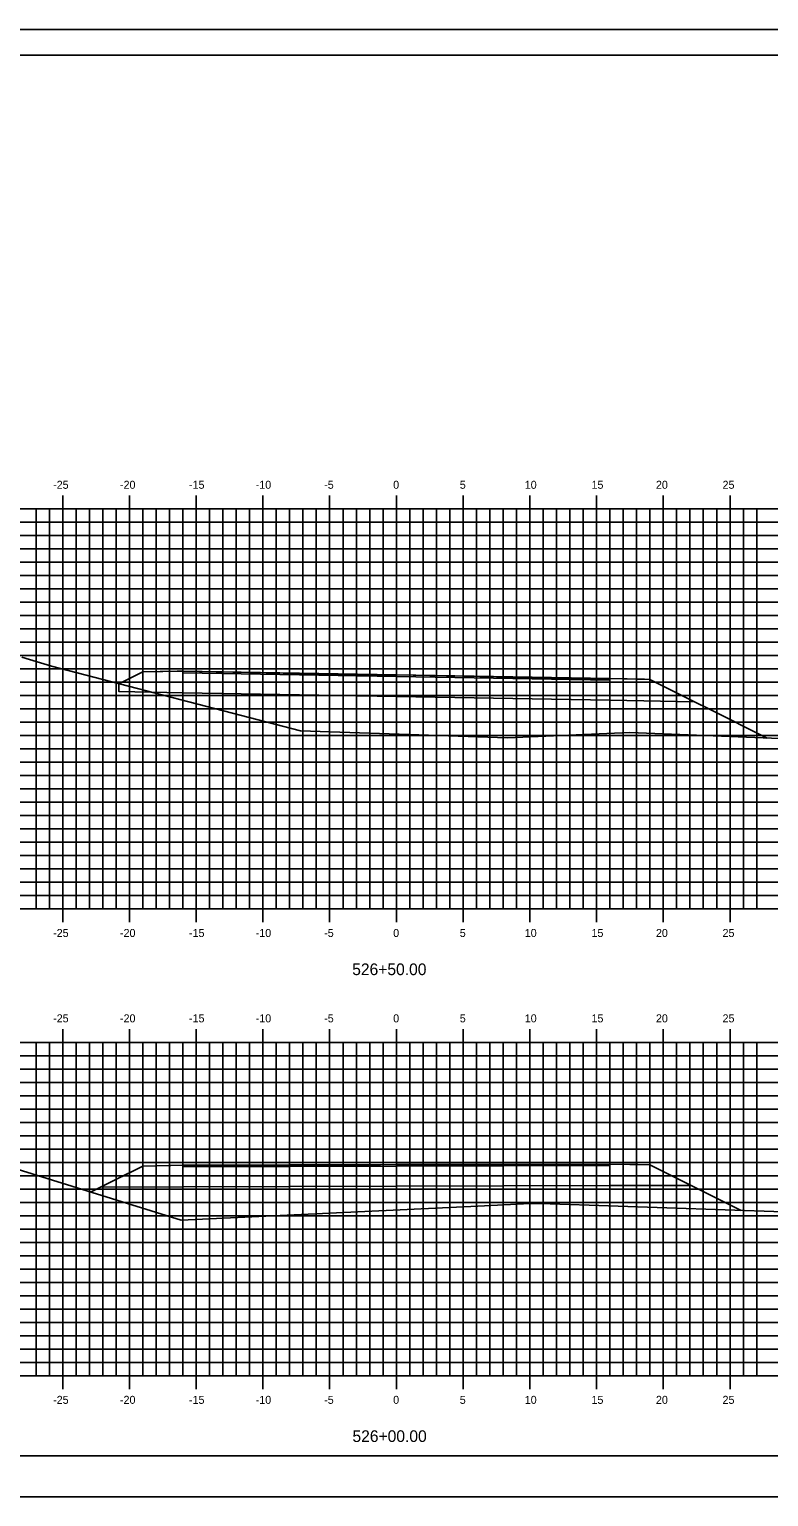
# Model space of a CAD drawing. Extents: x 1168600 to 1177589, y 610178 to 611246.
# Drawn here: x 1175921.1 to 1175976.5, y 610268.7 to 610378.7 of the extents above; entities that cross this region are included whole.
import ezdxf

# ---------------------------------------------------------------- set-up
doc = ezdxf.new("R2010")
doc.units = 0
for name, color, linetype in [('_Construction', 7, 'Continuous'), ('_Station Equation', 7, 'Continuous'), ('D_Roadway_Edge_TW', 7, 'Continuous'), ('D_Roadway_SubGrade', 7, 'Continuous'), ('D_Slope_Direction', 7, 'Continuous'), ('D_Text_Standard', 7, 'Continuous'), ('DIMENSIONS', 7, 'Continuous'), ('H_V ANNOTATION', 7, 'Continuous'), ('MAJOR', 7, 'Continuous'), ('MATCH LINES', 7, 'Continuous'), ('MINOR', 7, 'Continuous')]:
    doc.layers.add(name, color=color, linetype=linetype)

msp = doc.modelspace()

# ---------------------------------------------------------------- linework, layer by layer
at = {"layer": '_Construction'}
for p, q in [((1176033.63, 610376.8), (1175873.63, 610376.8)), ((1175873.63, 610271.8), (1176033.63, 610271.8))]:
    msp.add_line(p, q, dxfattribs=at)
msp.add_lwpolyline([(1175865.54, 610268.74), (1176035.54, 610268.74), (1176035.54, 610378.74), (1175865.54, 610378.74)], close=True, dxfattribs=at)
at = {"layer": '_Station Equation'}
for points in [[(1175920.56, 610331.68), (1175922.78, 610330.99), (1175941.45, 610326.15), (1175956.96, 610325.64), (1175966.12, 610326.02), (1175991.7, 610325.01)], [(1175917.61, 610294.1), (1175932.5, 610289.47), (1175954.73, 610290.51), (1175958.66, 610290.71), (1175960.16, 610290.69), (1175986.39, 610289.8)]]:
    msp.add_lwpolyline(points, dxfattribs=at)
at = {"layer": 'D_Roadway_Edge_TW'}
for points in [[(1175932.63, 610330.51), (1175932.63, 610330.63), (1175948.63, 610330.35), (1175964.63, 610330.07), (1175964.63, 610329.94), (1175948.63, 610330.22)], [(1175932.63, 610293.46), (1175932.63, 610293.59), (1175948.63, 610293.64), (1175964.63, 610293.68), (1175964.63, 610293.56), (1175948.63, 610293.51)]]:
    msp.add_lwpolyline(points, close=True, dxfattribs=at)
at = {"layer": 'D_Roadway_SubGrade'}
for points in [[(1175932.63, 610330.63), (1175929.63, 610330.57), (1175927.84, 610329.68), (1175927.84, 610329.09), (1175932.63, 610329.01)], [(1175932.63, 610329.01), (1175932.63, 610330.51), (1175948.63, 610330.22), (1175964.63, 610329.94), (1175964.63, 610328.44), (1175948.63, 610328.72)], [(1175964.63, 610330.07), (1175967.63, 610330.01), (1175970.98, 610328.33), (1175964.63, 610328.44)], [(1175932.63, 610293.59), (1175929.63, 610293.53), (1175926.46, 610291.94), (1175932.63, 610291.96)], [(1175932.63, 610291.96), (1175932.63, 610293.46), (1175948.63, 610293.51), (1175964.63, 610293.56), (1175964.63, 610292.06), (1175948.63, 610292.01)], [(1175964.63, 610293.68), (1175967.63, 610293.62), (1175970.72, 610292.07), (1175964.63, 610292.06)]]:
    msp.add_lwpolyline(points, close=True, dxfattribs=at)
at = {"layer": 'D_Slope_Direction'}
msp.add_lwpolyline([(1175929.63, 610330.57), (1175927.89, 610329.7)], dxfattribs=at)
at = {"layer": 'D_Text_Standard'}
for points in [[(1175927.84, 610329.68), (1175927.84, 610329.68), (1175927.89, 610329.7), (1175929.14, 610330.33), (1175929.63, 610330.57), (1175932.21, 610330.62), (1175932.63, 610330.63), (1175946.38, 610330.36), (1175948.63, 610330.35), (1175962.38, 610330.07), (1175964.63, 610330.07), (1175967.21, 610330.02), (1175967.63, 610330.01), (1175968.07, 610329.78), (1175970.98, 610328.33), (1175972.09, 610327.77), (1175976.42, 610325.61)], [(1175925.72, 610291.58), (1175926.32, 610291.88), (1175926.46, 610291.94), (1175927.46, 610292.45), (1175929.63, 610293.53), (1175931.73, 610293.57), (1175932.63, 610293.59), (1175943.83, 610293.55), (1175948.63, 610293.64), (1175959.83, 610293.6), (1175964.63, 610293.68), (1175966.73, 610293.64), (1175967.63, 610293.62), (1175968.51, 610293.18), (1175970.72, 610292.07), (1175973.17, 610290.85), (1175974.47, 610290.2)]]:
    msp.add_lwpolyline(points, dxfattribs=at)
at = {"layer": 'DIMENSIONS'}
for points in [[(1175932.63, 610330.51), (1175932.63, 610330.51), (1175948.63, 610330.22), (1175964.63, 610329.94), (1175964.63, 610329.94), (1175948.63, 610330.22)], [(1175932.63, 610293.46), (1175932.63, 610293.46), (1175948.63, 610293.51), (1175964.63, 610293.56), (1175964.63, 610293.56), (1175948.63, 610293.51)]]:
    msp.add_lwpolyline(points, close=True, dxfattribs=at)
for points in [[(1175932.63, 610330.51), (1175932.63, 610330.51)], [(1175932.63, 610330.51), (1175932.63, 610330.51)], [(1175964.63, 610329.94), (1175964.63, 610329.94)], [(1175964.63, 610329.94), (1175964.63, 610329.94)], [(1175932.63, 610293.46), (1175932.63, 610293.46)], [(1175932.63, 610293.46), (1175932.63, 610293.46)], [(1175964.63, 610293.56), (1175964.63, 610293.56)], [(1175964.63, 610293.56), (1175964.63, 610293.56)]]:
    msp.add_lwpolyline(points, dxfattribs=at)
at = {"layer": 'MAJOR'}
for p, q in [((1175923.63, 610343.8), (1175923.63, 610342.8)), ((1175928.63, 610343.8), (1175928.63, 610342.8)), ((1175933.63, 610343.8), (1175933.63, 610342.8)), ((1175938.63, 610343.8), (1175938.63, 610342.8)), ((1175943.63, 610343.8), (1175943.63, 610342.8)), ((1175948.63, 610343.8), (1175948.63, 610342.8)), ((1175953.63, 610343.8), (1175953.63, 610342.8)), ((1175958.63, 610343.8), (1175958.63, 610342.8)), ((1175963.63, 610343.8), (1175963.63, 610342.8)), ((1175968.63, 610343.8), (1175968.63, 610342.8)), ((1175973.63, 610343.8), (1175973.63, 610342.8)), ((1175878.63, 610342.8), (1176018.63, 610342.8)), ((1175878.63, 610342.8), (1176018.63, 610342.8)), ((1175923.63, 610312.8), (1175923.63, 610342.8)), ((1175928.63, 610312.8), (1175928.63, 610342.8)), ((1175933.63, 610312.8), (1175933.63, 610342.8)), ((1175938.63, 610312.8), (1175938.63, 610342.8)), ((1175943.63, 610312.8), (1175943.63, 610342.8)), ((1175948.63, 610312.8), (1175948.63, 610342.8)), ((1175953.63, 610312.8), (1175953.63, 610342.8)), ((1175958.63, 610312.8), (1175958.63, 610342.8)), ((1175963.63, 610312.8), (1175963.63, 610342.8)), ((1175968.63, 610312.8), (1175968.63, 610342.8)), ((1175973.63, 610312.8), (1175973.63, 610342.8)), ((1175878.63, 610337.8), (1176018.63, 610337.8)), ((1175878.63, 610332.8), (1176018.63, 610332.8)), ((1175878.63, 610327.8), (1176018.63, 610327.8)), ((1175878.63, 610322.8), (1176018.63, 610322.8)), ((1175878.63, 610317.8), (1176018.63, 610317.8)), ((1175878.63, 610312.8), (1176018.63, 610312.8)), ((1175878.63, 610312.8), (1176018.63, 610312.8)), ((1175923.63, 610311.8), (1175923.63, 610312.8)), ((1175928.63, 610311.8), (1175928.63, 610312.8)), ((1175933.63, 610311.8), (1175933.63, 610312.8)), ((1175938.63, 610311.8), (1175938.63, 610312.8)), ((1175943.63, 610311.8), (1175943.63, 610312.8)), ((1175948.63, 610311.8), (1175948.63, 610312.8)), ((1175953.63, 610311.8), (1175953.63, 610312.8)), ((1175958.63, 610311.8), (1175958.63, 610312.8)), ((1175963.63, 610311.8), (1175963.63, 610312.8)), ((1175968.63, 610311.8), (1175968.63, 610312.8)), ((1175973.63, 610311.8), (1175973.63, 610312.8)), ((1175923.63, 610303.8), (1175923.63, 610302.8)), ((1175928.63, 610303.8), (1175928.63, 610302.8)), ((1175933.63, 610303.8), (1175933.63, 610302.8)), ((1175938.63, 610303.8), (1175938.63, 610302.8)), ((1175943.63, 610303.8), (1175943.63, 610302.8)), ((1175948.63, 610303.8), (1175948.63, 610302.8)), ((1175953.63, 610303.8), (1175953.63, 610302.8)), ((1175958.63, 610303.8), (1175958.63, 610302.8)), ((1175963.63, 610303.8), (1175963.63, 610302.8)), ((1175968.63, 610303.8), (1175968.63, 610302.8)), ((1175973.63, 610303.8), (1175973.63, 610302.8)), ((1175878.63, 610302.8), (1176018.63, 610302.8)), ((1175878.63, 610302.8), (1176018.63, 610302.8)), ((1175923.63, 610277.8), (1175923.63, 610302.8)), ((1175928.63, 610277.8), (1175928.63, 610302.8)), ((1175933.63, 610277.8), (1175933.63, 610302.8)), ((1175938.63, 610277.8), (1175938.63, 610302.8)), ((1175943.63, 610277.8), (1175943.63, 610302.8)), ((1175948.63, 610277.8), (1175948.63, 610302.8)), ((1175953.63, 610277.8), (1175953.63, 610302.8)), ((1175958.63, 610277.8), (1175958.63, 610302.8)), ((1175963.63, 610277.8), (1175963.63, 610302.8)), ((1175968.63, 610277.8), (1175968.63, 610302.8)), ((1175973.63, 610277.8), (1175973.63, 610302.8)), ((1175878.63, 610297.8), (1176018.63, 610297.8)), ((1175878.63, 610292.8), (1176018.63, 610292.8)), ((1175878.63, 610287.8), (1176018.63, 610287.8)), ((1175878.63, 610282.8), (1176018.63, 610282.8)), ((1175878.63, 610277.8), (1176018.63, 610277.8)), ((1175878.63, 610277.8), (1176018.63, 610277.8)), ((1175923.63, 610276.8), (1175923.63, 610277.8)), ((1175928.63, 610276.8), (1175928.63, 610277.8)), ((1175933.63, 610276.8), (1175933.63, 610277.8)), ((1175938.63, 610276.8), (1175938.63, 610277.8)), ((1175943.63, 610276.8), (1175943.63, 610277.8)), ((1175948.63, 610276.8), (1175948.63, 610277.8)), ((1175953.63, 610276.8), (1175953.63, 610277.8)), ((1175958.63, 610276.8), (1175958.63, 610277.8)), ((1175963.63, 610276.8), (1175963.63, 610277.8)), ((1175968.63, 610276.8), (1175968.63, 610277.8)), ((1175973.63, 610276.8), (1175973.63, 610277.8))]:
    msp.add_line(p, q, dxfattribs=at)
at = {"layer": 'MATCH LINES'}
for points in [[(1175932.63, 610330.63), (1175932.63, 610330.51)], [(1175964.63, 610330.07), (1175964.63, 610329.94)], [(1175932.63, 610293.59), (1175932.63, 610293.46)], [(1175964.63, 610293.68), (1175964.63, 610293.56)]]:
    msp.add_lwpolyline(points, dxfattribs=at)
at = {"layer": 'MINOR'}
for p, q in [((1175921.63, 610312.8), (1175921.63, 610342.8)), ((1175922.63, 610312.8), (1175922.63, 610342.8)), ((1175924.63, 610312.8), (1175924.63, 610342.8)), ((1175925.63, 610312.8), (1175925.63, 610342.8)), ((1175926.63, 610312.8), (1175926.63, 610342.8)), ((1175927.63, 610312.8), (1175927.63, 610342.8)), ((1175929.63, 610312.8), (1175929.63, 610342.8)), ((1175930.63, 610312.8), (1175930.63, 610342.8)), ((1175931.63, 610312.8), (1175931.63, 610342.8)), ((1175932.63, 610312.8), (1175932.63, 610342.8)), ((1175934.63, 610312.8), (1175934.63, 610342.8)), ((1175935.63, 610312.8), (1175935.63, 610342.8)), ((1175936.63, 610312.8), (1175936.63, 610342.8)), ((1175937.63, 610312.8), (1175937.63, 610342.8)), ((1175939.63, 610312.8), (1175939.63, 610342.8)), ((1175940.63, 610312.8), (1175940.63, 610342.8)), ((1175941.63, 610312.8), (1175941.63, 610342.8)), ((1175942.63, 610312.8), (1175942.63, 610342.8)), ((1175944.63, 610312.8), (1175944.63, 610342.8)), ((1175945.63, 610312.8), (1175945.63, 610342.8)), ((1175946.63, 610312.8), (1175946.63, 610342.8)), ((1175947.63, 610312.8), (1175947.63, 610342.8)), ((1175949.63, 610312.8), (1175949.63, 610342.8)), ((1175950.63, 610312.8), (1175950.63, 610342.8)), ((1175951.63, 610312.8), (1175951.63, 610342.8)), ((1175952.63, 610312.8), (1175952.63, 610342.8)), ((1175954.63, 610312.8), (1175954.63, 610342.8)), ((1175955.63, 610312.8), (1175955.63, 610342.8)), ((1175956.63, 610312.8), (1175956.63, 610342.8)), ((1175957.63, 610312.8), (1175957.63, 610342.8)), ((1175959.63, 610312.8), (1175959.63, 610342.8)), ((1175960.63, 610312.8), (1175960.63, 610342.8)), ((1175961.63, 610312.8), (1175961.63, 610342.8)), ((1175962.63, 610312.8), (1175962.63, 610342.8)), ((1175964.63, 610312.8), (1175964.63, 610342.8)), ((1175965.63, 610312.8), (1175965.63, 610342.8)), ((1175966.63, 610312.8), (1175966.63, 610342.8)), ((1175967.63, 610312.8), (1175967.63, 610342.8)), ((1175969.63, 610312.8), (1175969.63, 610342.8)), ((1175970.63, 610312.8), (1175970.63, 610342.8)), ((1175971.63, 610312.8), (1175971.63, 610342.8)), ((1175972.63, 610312.8), (1175972.63, 610342.8)), ((1175974.63, 610312.8), (1175974.63, 610342.8)), ((1175975.63, 610312.8), (1175975.63, 610342.8)), ((1175878.63, 610341.8), (1176018.63, 610341.8)), ((1175878.63, 610340.8), (1176018.63, 610340.8)), ((1175878.63, 610339.8), (1176018.63, 610339.8)), ((1175878.63, 610338.8), (1176018.63, 610338.8)), ((1175878.63, 610336.8), (1176018.63, 610336.8)), ((1175878.63, 610335.8), (1176018.63, 610335.8)), ((1175878.63, 610334.8), (1176018.63, 610334.8)), ((1175878.63, 610333.8), (1176018.63, 610333.8)), ((1175878.63, 610331.8), (1176018.63, 610331.8)), ((1175878.63, 610330.8), (1176018.63, 610330.8)), ((1175878.63, 610329.8), (1176018.63, 610329.8)), ((1175878.63, 610328.8), (1176018.63, 610328.8)), ((1175878.63, 610326.8), (1176018.63, 610326.8)), ((1175878.63, 610325.8), (1176018.63, 610325.8)), ((1175878.63, 610324.8), (1176018.63, 610324.8)), ((1175878.63, 610323.8), (1176018.63, 610323.8)), ((1175878.63, 610321.8), (1176018.63, 610321.8)), ((1175878.63, 610320.8), (1176018.63, 610320.8)), ((1175878.63, 610319.8), (1176018.63, 610319.8)), ((1175878.63, 610318.8), (1176018.63, 610318.8)), ((1175878.63, 610316.8), (1176018.63, 610316.8)), ((1175878.63, 610315.8), (1176018.63, 610315.8)), ((1175878.63, 610314.8), (1176018.63, 610314.8)), ((1175878.63, 610313.8), (1176018.63, 610313.8)), ((1175921.63, 610277.8), (1175921.63, 610302.8)), ((1175922.63, 610277.8), (1175922.63, 610302.8)), ((1175924.63, 610277.8), (1175924.63, 610302.8)), ((1175925.63, 610277.8), (1175925.63, 610302.8)), ((1175926.63, 610277.8), (1175926.63, 610302.8)), ((1175927.63, 610277.8), (1175927.63, 610302.8)), ((1175929.63, 610277.8), (1175929.63, 610302.8)), ((1175930.63, 610277.8), (1175930.63, 610302.8)), ((1175931.63, 610277.8), (1175931.63, 610302.8)), ((1175932.63, 610277.8), (1175932.63, 610302.8)), ((1175934.63, 610277.8), (1175934.63, 610302.8)), ((1175935.63, 610277.8), (1175935.63, 610302.8)), ((1175936.63, 610277.8), (1175936.63, 610302.8)), ((1175937.63, 610277.8), (1175937.63, 610302.8)), ((1175939.63, 610277.8), (1175939.63, 610302.8)), ((1175940.63, 610277.8), (1175940.63, 610302.8)), ((1175941.63, 610277.8), (1175941.63, 610302.8)), ((1175942.63, 610277.8), (1175942.63, 610302.8)), ((1175944.63, 610277.8), (1175944.63, 610302.8)), ((1175945.63, 610277.8), (1175945.63, 610302.8)), ((1175946.63, 610277.8), (1175946.63, 610302.8)), ((1175947.63, 610277.8), (1175947.63, 610302.8)), ((1175949.63, 610277.8), (1175949.63, 610302.8)), ((1175950.63, 610277.8), (1175950.63, 610302.8)), ((1175951.63, 610277.8), (1175951.63, 610302.8)), ((1175952.63, 610277.8), (1175952.63, 610302.8)), ((1175954.63, 610277.8), (1175954.63, 610302.8)), ((1175955.63, 610277.8), (1175955.63, 610302.8)), ((1175956.63, 610277.8), (1175956.63, 610302.8)), ((1175957.63, 610277.8), (1175957.63, 610302.8)), ((1175959.63, 610277.8), (1175959.63, 610302.8)), ((1175960.63, 610277.8), (1175960.63, 610302.8)), ((1175961.63, 610277.8), (1175961.63, 610302.8)), ((1175962.63, 610277.8), (1175962.63, 610302.8)), ((1175964.63, 610277.8), (1175964.63, 610302.8)), ((1175965.63, 610277.8), (1175965.63, 610302.8)), ((1175966.63, 610277.8), (1175966.63, 610302.8)), ((1175967.63, 610277.8), (1175967.63, 610302.8)), ((1175969.63, 610277.8), (1175969.63, 610302.8)), ((1175970.63, 610277.8), (1175970.63, 610302.8)), ((1175971.63, 610277.8), (1175971.63, 610302.8)), ((1175972.63, 610277.8), (1175972.63, 610302.8)), ((1175974.63, 610277.8), (1175974.63, 610302.8)), ((1175975.63, 610277.8), (1175975.63, 610302.8)), ((1175878.63, 610301.8), (1176018.63, 610301.8)), ((1175878.63, 610300.8), (1176018.63, 610300.8)), ((1175878.63, 610299.8), (1176018.63, 610299.8)), ((1175878.63, 610298.8), (1176018.63, 610298.8)), ((1175878.63, 610296.8), (1176018.63, 610296.8)), ((1175878.63, 610295.8), (1176018.63, 610295.8)), ((1175878.63, 610294.8), (1176018.63, 610294.8)), ((1175878.63, 610293.8), (1176018.63, 610293.8)), ((1175878.63, 610291.8), (1176018.63, 610291.8)), ((1175878.63, 610290.8), (1176018.63, 610290.8)), ((1175878.63, 610289.8), (1176018.63, 610289.8)), ((1175878.63, 610288.8), (1176018.63, 610288.8)), ((1175878.63, 610286.8), (1176018.63, 610286.8)), ((1175878.63, 610285.8), (1176018.63, 610285.8)), ((1175878.63, 610284.8), (1176018.63, 610284.8)), ((1175878.63, 610283.8), (1176018.63, 610283.8)), ((1175878.63, 610281.8), (1176018.63, 610281.8)), ((1175878.63, 610280.8), (1176018.63, 610280.8)), ((1175878.63, 610279.8), (1176018.63, 610279.8)), ((1175878.63, 610278.8), (1176018.63, 610278.8))]:
    msp.add_line(p, q, dxfattribs=at)

# ---------------------------------------------------------------- texts
at = {"layer": 'D_Text_Standard'}
for s, p in [('C', (1175948.62, 610330.35)), ('L', (1175948.63, 610330.34)), ('C', (1175948.62, 610293.64)), ('L', (1175948.63, 610293.63))]:
    msp.add_text(s, height=0.0146, dxfattribs=at).set_placement(p)
at = {"layer": 'H_V ANNOTATION'}
for s, height, p in [('-25', 0.6, (1175922.91, 610344.3)), ('-20', 0.6, (1175927.92, 610344.3)), ('-15', 0.6, (1175933.09, 610344.3)), ('-10', 0.6, (1175938.09, 610344.3)), ('-5', 0.6, (1175943.22, 610344.3)), ('0', 0.6, (1175948.39, 610344.3)), ('5', 0.6, (1175953.38, 610344.3)), ('10', 0.6, (1175958.25, 610344.3)), ('15', 0.6, (1175963.25, 610344.3)), ('20', 0.6, (1175968.08, 610344.3)), ('25', 0.6, (1175973.07, 610344.3)), ('-25', 0.6, (1175922.91, 610310.7)), ('-20', 0.6, (1175927.92, 610310.7)), ('-15', 0.6, (1175933.09, 610310.7)), ('-10', 0.6, (1175938.09, 610310.7)), ('-5', 0.6, (1175943.22, 610310.7)), ('0', 0.6, (1175948.39, 610310.7)), ('5', 0.6, (1175953.38, 610310.7)), ('10', 0.6, (1175958.25, 610310.7)), ('15', 0.6, (1175963.25, 610310.7)), ('20', 0.6, (1175968.08, 610310.7)), ('25', 0.6, (1175973.07, 610310.7)), ('526+50.00', 0.875, (1175945.32, 610307.84)), ('-25', 0.6, (1175922.91, 610304.3)), ('-20', 0.6, (1175927.92, 610304.3)), ('-15', 0.6, (1175933.09, 610304.3)), ('-10', 0.6, (1175938.09, 610304.3)), ('-5', 0.6, (1175943.22, 610304.3)), ('0', 0.6, (1175948.39, 610304.3)), ('5', 0.6, (1175953.38, 610304.3)), ('10', 0.6, (1175958.25, 610304.3)), ('15', 0.6, (1175963.25, 610304.3)), ('20', 0.6, (1175968.08, 610304.3)), ('25', 0.6, (1175973.07, 610304.3)), ('-25', 0.6, (1175922.91, 610275.7)), ('-20', 0.6, (1175927.92, 610275.7)), ('-15', 0.6, (1175933.09, 610275.7)), ('-10', 0.6, (1175938.09, 610275.7)), ('-5', 0.6, (1175943.22, 610275.7)), ('0', 0.6, (1175948.39, 610275.7)), ('5', 0.6, (1175953.38, 610275.7)), ('10', 0.6, (1175958.25, 610275.7)), ('15', 0.6, (1175963.25, 610275.7)), ('20', 0.6, (1175968.08, 610275.7)), ('25', 0.6, (1175973.07, 610275.7)), ('526+00.00', 0.875, (1175945.34, 610272.84))]:
    msp.add_text(s, height=height, dxfattribs=at).set_placement(p)

doc.saveas('drawing.dxf')
